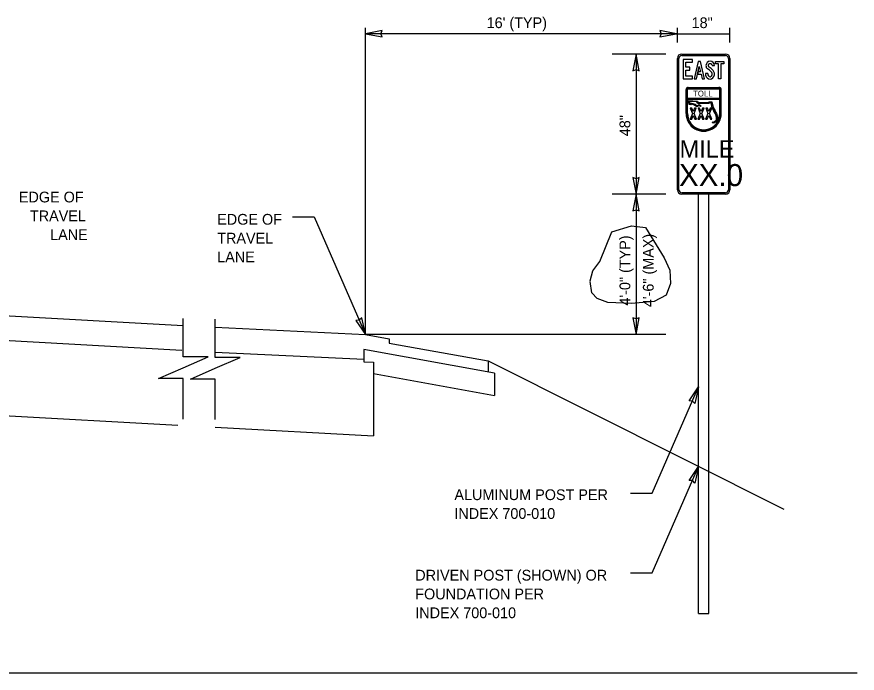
# Model space of a CAD drawing. Extents: x 56768 to 57406, y 11696 to 12105.
# Drawn here: x 57187.3 to 57405.9, y 11934.3 to 12105.2 of the extents above; entities that cross this region are included whole.
import ezdxf

# ---------------------------------------------------------------- set-up
doc = ezdxf.new("R2010")
doc.units = 0
for name, color, linetype in [('1', 7, 'Continuous'), ('52', 7, 'Continuous'), ('62', 7, 'Continuous'), ('Default', 7, 'Continuous'), ('DimLines_dp', 7, 'Continuous'), ('SheetBorder_dp', 7, 'Continuous'), ('SignPanel', 7, 'Continuous'), ('XSGrdLine_ex', 7, 'Continuous')]:
    doc.layers.add(name, color=color, linetype=linetype)

msp = doc.modelspace()

# ---------------------------------------------------------------- linework, layer by layer
at = {"layer": '1'}
for p, q in [((57364.62, 11988.09), (57364.62, 12058.97)), ((57367.28, 11986.75), (57367.28, 12058.97)), ((57364.62, 11949.76), (57364.62, 11988.09)), ((57367.28, 11949.76), (57367.28, 11986.75)), ((57364.62, 11949.76), (57367.28, 11949.76))]:
    msp.add_line(p, q, dxfattribs=at)
at = {"layer": '52'}
msp.add_line((57356.11, 12022.47), (57277.99, 12022.47), dxfattribs=at)
at = {"layer": '62'}
msp.add_lwpolyline([(57336.45, 12036.41), (57337.15, 12039.01), (57338.95, 12041.42), (57342.06, 12049.17), (57347.16, 12050.77), (57350.86, 12050.27), (57355.66, 12042.42), (57357.16, 12039.21), (57357.36, 12035.71), (57356.16, 12032.7), (57353.06, 12031), (57347.16, 12030.5), (57341.05, 12030.8), (57338.25, 12031.8), (57336.85, 12033.31), (57336.45, 12036.21)], dxfattribs=at)
at = {"layer": 'Default'}
for points in [[(57230.6, 12000.41), (57230.6, 12010.97), (57224.14, 12010.97), (57230.6, 12013.79), (57237.06, 12016.6), (57230.6, 12016.6), (57230.6, 12026.6)], [(57238.9, 12000.28), (57238.9, 12010.84), (57232.44, 12010.84), (57238.9, 12013.65), (57245.36, 12016.47), (57238.9, 12016.47), (57238.9, 12026.47)]]:
    msp.add_lwpolyline(points, dxfattribs=at)
at = {"layer": 'DimLines_dp'}
for p, q in [((57277.99, 12022.47), (57277.99, 12102.3)), ((57359.11, 12098.47), (57359.11, 12102.3)), ((57372.79, 12098.47), (57372.79, 12102.3)), ((57282.34, 12101.56), (57277.99, 12100.75)), ((57359.11, 12100.75), (57277.99, 12100.75)), ((57277.99, 12100.75), (57282.34, 12099.91)), ((57282.01, 12100.75), (57282.34, 12101.56)), ((57282.34, 12099.91), (57282.01, 12100.75)), ((57358.92, 12100.75), (57354.57, 12101.59)), ((57354.57, 12101.59), (57354.9, 12100.75)), ((57354.9, 12100.75), (57354.57, 12099.94)), ((57354.57, 12099.94), (57358.92, 12100.75)), ((57359.11, 12100.75), (57372.79, 12100.75)), ((57356.11, 12095.47), (57342.18, 12095.47)), ((57348.36, 12095.47), (57347.52, 12091.12)), ((57348.36, 12095.47), (57348.36, 12058.97)), ((57349.17, 12091.12), (57348.36, 12095.47)), ((57347.52, 12091.12), (57348.36, 12091.45)), ((57348.36, 12091.45), (57349.17, 12091.12)), ((57348.36, 12062.99), (57347.55, 12063.32)), ((57347.55, 12063.32), (57348.36, 12058.97)), ((57348.36, 12062.99), (57347.55, 12063.32)), ((57347.55, 12063.32), (57348.36, 12058.97)), ((57348.36, 12058.97), (57349.2, 12063.32)), ((57349.2, 12063.32), (57348.36, 12062.99)), ((57348.36, 12058.97), (57349.2, 12063.32)), ((57349.2, 12063.32), (57348.36, 12062.99)), ((57356.11, 12058.97), (57342.18, 12058.97)), ((57348.36, 12058.97), (57347.52, 12054.62)), ((57348.36, 12058.97), (57348.36, 12022.47)), ((57349.17, 12054.62), (57348.36, 12058.97)), ((57347.52, 12054.62), (57348.36, 12054.95)), ((57348.36, 12054.95), (57349.17, 12054.62)), ((57259.02, 12053.08), (57264.67, 12053.08)), ((57264.67, 12053.08), (57277.99, 12022.46)), ((57276.38, 12026.15), (57275.51, 12026.13)), ((57275.51, 12026.13), (57277.99, 12022.46)), ((57277.02, 12026.79), (57276.38, 12026.15)), ((57277.99, 12022.46), (57277.02, 12026.79)), ((57348.36, 12026.49), (57347.55, 12026.82)), ((57347.55, 12026.82), (57348.36, 12022.47)), ((57348.36, 12022.47), (57349.2, 12026.82)), ((57349.2, 12026.82), (57348.36, 12026.49)), ((57352.58, 11981.13), (57364.62, 12008.81)), ((57362.14, 12005.14), (57364.62, 12008.81)), ((57364.62, 12008.81), (57363.65, 12004.48)), ((57363.01, 12005.12), (57362.14, 12005.14)), ((57363.65, 12004.48), (57363.01, 12005.12)), ((57352.58, 11960.41), (57364.62, 11988.09)), ((57362.14, 11984.42), (57364.62, 11988.09)), ((57364.62, 11988.09), (57363.65, 11983.76)), ((57363.01, 11984.4), (57362.14, 11984.42)), ((57363.65, 11983.76), (57363.01, 11984.4)), ((57346.93, 11981.13), (57352.58, 11981.13)), ((57346.93, 11960.41), (57352.58, 11960.41))]:
    msp.add_line(p, q, dxfattribs=at)
at = {"layer": 'SheetBorder_dp'}
msp.add_line((57405.89, 11934.25), (56789.89, 11934.25), dxfattribs=at)
at = {"layer": 'SignPanel'}
for p, q in [((57368.14, 12092.46), (57368.73, 12092.46)), ((57368.14, 12092.46), (57368.73, 12092.46)), ((57368.14, 12092.46), (57368.73, 12092.46)), ((57367.01, 12090.42), (57366.41, 12090.42)), ((57367.01, 12090.42), (57366.41, 12090.42)), ((57367.01, 12090.42), (57366.41, 12090.42)), ((57361.96, 12086.8), (57369.94, 12086.8)), ((57361.39, 12079.95), (57361.39, 12086.23)), ((57361.58, 12079.95), (57361.58, 12086.23)), ((57361.77, 12083.95), (57361.77, 12086.23)), ((57361.96, 12086.61), (57369.94, 12086.61)), ((57361.96, 12086.42), (57369.94, 12086.42)), ((57370.13, 12083.95), (57370.13, 12086.23)), ((57370.32, 12079.95), (57370.32, 12086.23)), ((57370.51, 12079.95), (57370.51, 12086.23)), ((57361.77, 12083.95), (57370.13, 12083.95)), ((57361.77, 12079.95), (57361.77, 12083.76)), ((57361.77, 12083.76), (57370.13, 12083.76)), ((57362.15, 12082.3), (57361.98, 12083.39)), ((57361.98, 12083.39), (57364.36, 12083.21)), ((57364.2, 12082.99), (57362.25, 12083.14)), ((57362.25, 12083.14), (57362.35, 12082.51)), ((57362.35, 12082.51), (57362.54, 12082.48)), ((57362.54, 12082.48), (57362.81, 12082.7)), ((57362.86, 12082.44), (57362.61, 12082.24)), ((57362.81, 12082.7), (57363.73, 12082.4)), ((57363.61, 12082.19), (57362.86, 12082.44)), ((57363.24, 12083.05), (57363.24, 12083.05)), ((57363.73, 12082.4), (57364.18, 12081.98)), ((57364.34, 12082.63), (57364.2, 12082.99)), ((57367.35, 12082.63), (57364.34, 12082.63)), ((57364.36, 12083.21), (57364.5, 12082.86)), ((57364.5, 12082.86), (57367.23, 12082.86)), ((57367.23, 12082.86), (57367.33, 12083.02)), ((57367.33, 12083.02), (57368.06, 12083.02)), ((57367.45, 12082.79), (57367.35, 12082.63)), ((57367.88, 12082.79), (57367.45, 12082.79)), ((57368.18, 12081.5), (57367.88, 12082.79)), ((57368.06, 12083.02), (57368.4, 12081.58)), ((57370.13, 12079.95), (57370.13, 12083.76)), ((57362.61, 12082.24), (57362.15, 12082.3)), ((57364.15, 12081.7), (57363.61, 12082.19)), ((57364.78, 12082.07), (57364.15, 12081.7)), ((57364.18, 12081.98), (57364.79, 12082.34)), ((57365.16, 12081.81), (57364.78, 12082.07)), ((57364.79, 12082.34), (57365.29, 12082)), ((57365.29, 12082), (57365.16, 12081.81)), ((57368.62, 12080.79), (57368.18, 12081.5)), ((57368.4, 12081.58), (57368.85, 12080.86)), ((57368.62, 12080.61), (57368.62, 12080.79)), ((57369.05, 12079.91), (57368.62, 12080.61)), ((57368.85, 12080.86), (57368.85, 12080.67)), ((57368.85, 12080.67), (57369.26, 12080)), ((57368.65, 12077.81), (57369.28, 12078.32)), ((57369.51, 12078.21), (57368.76, 12077.6)), ((57369.28, 12079.05), (57369.05, 12079.91)), ((57369.26, 12080), (57369.51, 12079.08)), ((57369.28, 12078.32), (57369.28, 12079.05)), ((57369.51, 12079.08), (57369.51, 12078.21)), ((57368.18, 12077.67), (57368.31, 12077.86)), ((57368.4, 12077.51), (57368.18, 12077.67)), ((57368.31, 12077.86), (57368.45, 12077.76)), ((57368.76, 12077.6), (57368.4, 12077.51)), ((57368.45, 12077.76), (57368.65, 12077.81))]:
    msp.add_line(p, q, dxfattribs=at)
for points in [[(57360.25, 12095.47), (57371.65, 12095.47)], [(57359.11, 12060.11), (57359.11, 12094.33)], [(57359.49, 12060.11), (57359.49, 12094.33)], [(57360.25, 12095.09), (57371.65, 12095.09)], [(57372.41, 12094.33), (57372.41, 12060.11)], [(57372.79, 12094.33), (57372.79, 12060.11)], [(57371.65, 12059.35), (57360.25, 12059.35)], [(57371.65, 12058.97), (57360.25, 12058.97)]]:
    msp.add_lwpolyline(points, dxfattribs=at)
for points in [[(57361.31, 12089.69), (57361.31, 12091.31), (57362.33, 12091.31), (57362.33, 12092.02), (57361.31, 12092.02), (57361.31, 12093.34), (57363.03, 12093.34), (57363.03, 12094.05), (57360.66, 12094.05), (57360.66, 12088.98), (57363.03, 12088.98), (57363.03, 12089.69)], [(57361.31, 12089.69), (57361.31, 12091.31), (57362.33, 12091.31), (57362.33, 12092.02), (57361.31, 12092.02), (57361.31, 12093.34), (57363.03, 12093.34), (57363.03, 12094.05), (57360.66, 12094.05), (57360.66, 12088.98), (57363.03, 12088.98), (57363.03, 12089.69)], [(57361.31, 12089.69), (57361.31, 12091.31), (57362.33, 12091.31), (57362.33, 12092.02), (57361.31, 12092.02), (57361.31, 12093.34), (57363.03, 12093.34), (57363.03, 12094.05), (57360.66, 12094.05), (57360.66, 12088.98), (57363.03, 12088.98), (57363.03, 12089.69)], [(57365.28, 12090.21), (57365.55, 12088.98), (57366.16, 12088.98), (57365.14, 12093.56), (57364.51, 12093.56), (57363.49, 12088.98), (57364.09, 12088.98), (57364.37, 12090.21)], [(57364.51, 12090.85), (57364.37, 12090.21), (57365.28, 12090.21), (57365.55, 12088.98), (57366.16, 12088.98), (57365.14, 12093.56), (57364.51, 12093.56), (57363.49, 12088.98), (57364.09, 12088.98), (57364.82, 12092.26), (57365.14, 12090.85)], [(57364.51, 12090.85), (57364.37, 12090.21), (57365.28, 12090.21), (57365.55, 12088.98), (57366.16, 12088.98), (57365.14, 12093.56), (57364.51, 12093.56), (57363.49, 12088.98), (57364.09, 12088.98), (57364.82, 12092.26), (57365.14, 12090.85)], [(57369.79, 12092.92), (57369.01, 12092.92), (57369.01, 12093.56), (57371.16, 12093.56), (57371.16, 12092.92), (57370.38, 12092.92), (57370.38, 12088.98), (57369.79, 12088.98)], [(57369.79, 12092.92), (57369.01, 12092.92), (57369.01, 12093.56), (57371.16, 12093.56), (57371.16, 12092.92), (57370.38, 12092.92), (57370.38, 12088.98), (57369.79, 12088.98)], [(57369.79, 12092.92), (57369.01, 12092.92), (57369.01, 12093.56), (57371.16, 12093.56), (57371.16, 12092.92), (57370.38, 12092.92), (57370.38, 12088.98), (57369.79, 12088.98)], [(57364.82, 12092.26), (57365.14, 12090.85), (57364.51, 12090.85)], [(57362.84, 12078.53), (57363.25, 12079.51), (57363.66, 12078.53), (57364.08, 12078.53), (57363.46, 12080.02), (57364.03, 12081.39), (57363.61, 12081.39), (57363.25, 12080.53), (57362.89, 12081.39), (57362.46, 12081.39), (57363.03, 12080.02), (57362.41, 12078.53)], [(57364.86, 12078.53), (57365.26, 12079.51), (57365.67, 12078.53), (57366.1, 12078.53), (57365.48, 12080.02), (57366.05, 12081.39), (57365.62, 12081.39), (57365.26, 12080.53), (57364.91, 12081.39), (57364.48, 12081.39), (57365.05, 12080.02), (57364.43, 12078.53)], [(57366.87, 12078.53), (57367.28, 12079.51), (57367.69, 12078.53), (57368.12, 12078.53), (57367.49, 12080.02), (57368.07, 12081.39), (57367.64, 12081.39), (57367.28, 12080.53), (57366.92, 12081.39), (57366.49, 12081.39), (57367.07, 12080.02), (57366.44, 12078.53)]]:
    msp.add_lwpolyline(points, close=True, dxfattribs=at)
for centre, radius, start, end in [((57360.25, 12094.33), 1.14, 90, 180), ((57371.65, 12094.33), 1.14, 0, 90), ((57360.25, 12094.33), 0.76, 90, 180), ((57371.65, 12094.33), 0.76, 0, 90), ((57360.25, 12060.11), 1.14, 180, 270), ((57360.25, 12060.11), 0.76, 180, 270), ((57371.65, 12060.11), 1.14, 270, 360), ((57371.65, 12060.11), 0.76, 270, 360)]:
    msp.add_arc(centre, radius, start, end, dxfattribs=at)
for centre, major_axis, ratio, start_param, end_param in [((57367.64, 12092.43), (0, 1.19), 0.91923, 4.736267, 7.790596), ((57367.64, 12092.43), (0, 1.19), 0.91923, 4.736267, 7.790596), ((57367.64, 12092.43), (0, 1.19), 0.91923, 4.736267, 7.790596), ((57367.53, 12092.47), (0, 1.07), 0.91923, 1.534831, 2.511766), ((57367.53, 12092.47), (0, 1.07), 0.91923, 1.534831, 2.511766), ((57367.53, 12092.47), (0, 1.07), 0.91923, 1.534831, 2.511766), ((57364.92, 12087.53), (0, 4.63), 0.91923, 5.515137, 5.786988), ((57364.92, 12087.53), (0, 4.63), 0.91923, 5.515137, 5.786988), ((57364.92, 12087.53), (0, 4.63), 0.91923, 5.515137, 5.786988), ((57367.57, 12092.49), (0, 0.46), 0.91923, 0.87378, 2.656959), ((57367.57, 12092.49), (0, 0.46), 0.91923, 0.87378, 2.656959), ((57367.57, 12092.49), (0, 0.46), 0.91923, 0.87378, 2.656959), ((57367.63, 12092.42), (0, 0.558), 0.91923, 4.786904, 7.140738), ((57367.63, 12092.42), (0, 0.558), 0.91923, 4.786904, 7.140738), ((57367.63, 12092.42), (0, 0.558), 0.91923, 4.786904, 7.140738), ((57365.43, 12088.23), (0, 4.39), 0.91923, 5.462886, 5.782242), ((57365.43, 12088.23), (0, 4.39), 0.91923, 5.462886, 5.782242), ((57365.43, 12088.23), (0, 4.39), 0.91923, 5.462886, 5.782242), ((57367.45, 12090.23), (0, 1.42), 0.91923, 4.260987, 5.485755), ((57367.45, 12090.23), (0, 1.42), 0.91923, 4.260987, 5.485755), ((57367.45, 12090.23), (0, 1.42), 0.91923, 4.260987, 5.485755), ((57367.79, 12090.35), (0, 1.5), 0.91923, 1.526364, 2.701682), ((57367.79, 12090.35), (0, 1.5), 0.91923, 1.526364, 2.701682), ((57367.79, 12090.35), (0, 1.5), 0.91923, 1.526364, 2.701682), ((57367.84, 12090.38), (0, 0.911), 0.91923, 1.524757, 2.28214), ((57367.84, 12090.38), (0, 0.911), 0.91923, 1.524757, 2.28214), ((57367.84, 12090.38), (0, 0.911), 0.91923, 1.524757, 2.28214), ((57367.6, 12090.17), (0, 1.24), 0.91923, 2.786047, 4.251692), ((57367.6, 12090.17), (0, 1.24), 0.91923, 2.786047, 4.251692), ((57367.6, 12090.17), (0, 1.24), 0.91923, 2.786047, 4.251692), ((57367.62, 12090.15), (0, 0.581), 0.91923, 2.261787, 4.23006), ((57367.62, 12090.15), (0, 0.581), 0.91923, 2.261787, 4.23006), ((57367.62, 12090.15), (0, 0.581), 0.91923, 2.261787, 4.23006), ((57367.44, 12090.23), (0, 0.792), 0.91923, 4.254409, 5.632398), ((57367.44, 12090.23), (0, 0.792), 0.91923, 4.254409, 5.632398), ((57367.44, 12090.23), (0, 0.792), 0.91923, 4.254409, 5.632398), ((57361.96, 12086.23), (0, 0.57), 0.9997, 0, 1.570796), ((57369.94, 12086.23), (0, 0.57), 0.9997, 4.712389, 6.283185), ((57361.96, 12086.23), (0, 0.38), 0.9997, 0, 1.570796), ((57361.96, 12086.23), (0, 0.19), 0.9997, 0, 1.570796), ((57369.94, 12086.23), (0, 0.38), 0.9997, 4.712389, 6.283185), ((57369.94, 12086.23), (0, 0.19), 0.9997, 4.712389, 6.283185), ((57365.95, 12079.95), (0, -4.56), 0.9997, 4.712389, 7.853982), ((57365.95, 12079.95), (0, -4.37), 0.9997, 4.712389, 7.853982), ((57365.95, 12079.95), (0, -4.18), 0.9997, 4.712389, 7.853982)]:
    msp.add_ellipse(centre, major_axis=major_axis, ratio=ratio, start_param=start_param, end_param=end_param, dxfattribs=at)
at = {"layer": 'XSGrdLine_ex'}
for p, q in [((57167.72, 12028.26), (57230.6, 12024.78)), ((57230.24, 12018.3), (57168, 12021.75)), ((57277.99, 12022.46), (57284.15, 12021.36)), ((57284.15, 12021.36), (57284.15, 12020.18)), ((57284.15, 12020.18), (57309.87, 12015.55)), ((57277.57, 12018.53), (57277.57, 12015.37)), ((57311.57, 12012.41), (57277.57, 12018.53)), ((57277.57, 12015.37), (57280.04, 12015.22)), ((57280.04, 12015.22), (57280.04, 11996.05)), ((57309.87, 12015.55), (57309.87, 12012.71)), ((57311.57, 12012.41), (57311.57, 12006.59)), ((57280.04, 12012.26), (57311.57, 12006.59)), ((57167.12, 12002.3), (57229.16, 11998.86)), ((57238.9, 11998.32), (57280.04, 11996.05))]:
    msp.add_line(p, q, dxfattribs=at)
for points in [[(57238.9, 12024.32), (57277.99, 12022.46)], [(57238.9, 12017.82), (57277.57, 12015.99)], [(57309.87, 12015.55), (57386.82, 11976.95)]]:
    msp.add_lwpolyline(points, dxfattribs=at)

# ---------------------------------------------------------------- texts
at = {"layer": 'DimLines_dp'}
for s, p in [("16' (TYP)", (57309.5, 12102.22)), ('18"', (57362.81, 12102.22)), ('EDGE OF ', (57187.82, 12056.84)), ('TRAVEL ', (57190.69, 12051.94)), ('EDGE OF ', (57239.41, 12051.04)), ('LANE', (57195.95, 12047.04)), ('TRAVEL ', (57239.41, 12046.14)), ('LANE', (57239.41, 12041.24)), ('ALUMINUM POST PER', (57301.11, 11979.33)), ('INDEX 700-010', (57301.11, 11974.43)), ('DRIVEN POST (SHOWN) OR', (57290.93, 11958.38)), ('FOUNDATION PER', (57290.93, 11953.48)), ('INDEX 700-010', (57290.93, 11948.58))]:
    msp.add_text(s, height=2.8, dxfattribs=at).set_placement(p)
for s, p in [('48"', (57346.87, 12074.08)), ('4\'-0" (TYP)', (57346.87, 12029.97)), ('4\'-6" (MAX)', (57352.95, 12029.57))]:
    msp.add_text(s, height=2.8, rotation=90, dxfattribs=at).set_placement(p)
at = {"layer": 'SignPanel'}
for s, height, p in [('TOLL', 1.519, (57363.19, 12084.42)), ('MILE', 4.562, (57359.7, 12068.47))]:
    msp.add_text(s, height=height, dxfattribs=at).set_placement(p)
msp.add_text('XX.0', height=5.75, rotation=360, dxfattribs=at).set_placement((57359.54, 12061.07))

doc.saveas('drawing.dxf')
